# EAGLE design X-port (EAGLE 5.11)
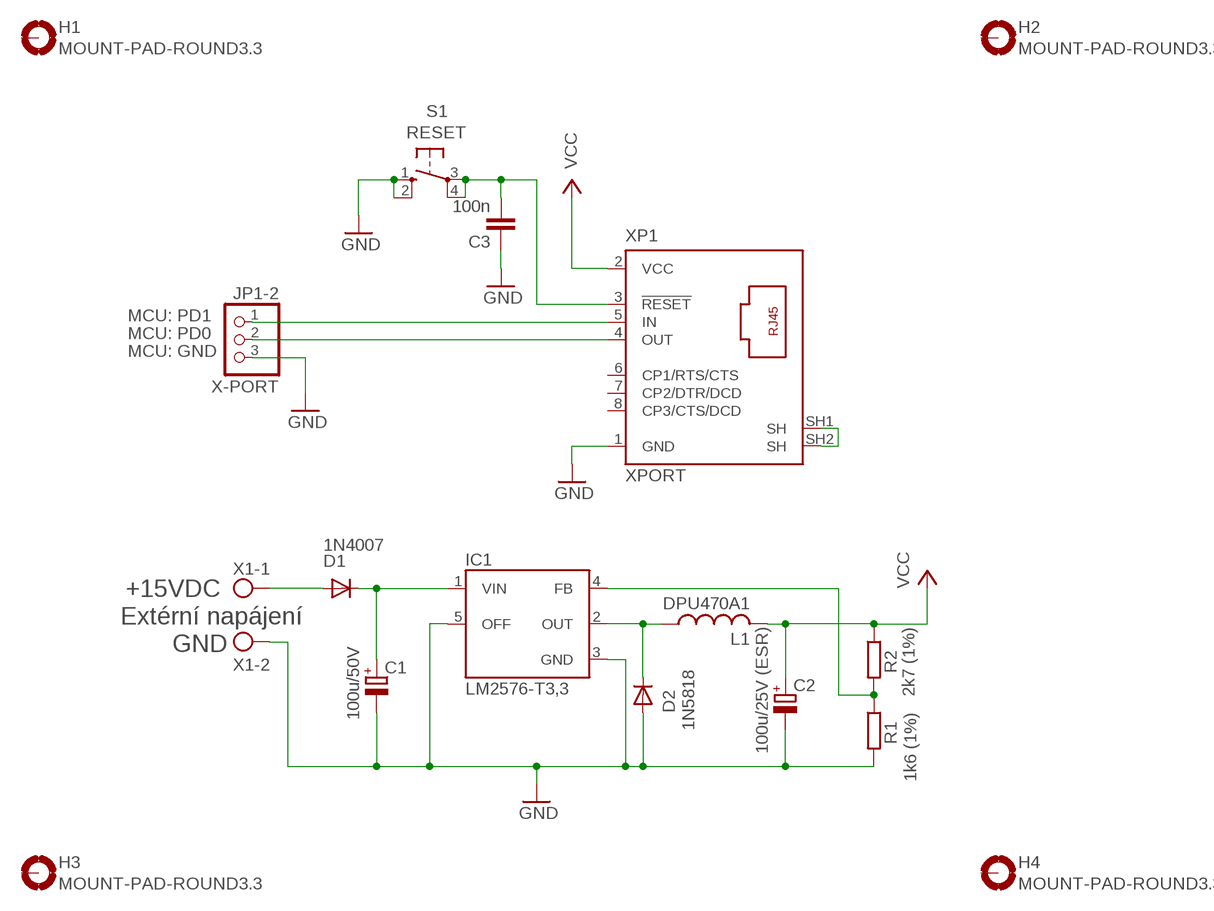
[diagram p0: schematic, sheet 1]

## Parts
C1  100u/50V  CPOL-EUE3.5-8  [E3,5-8]
C2  100u/25V (ESR)  CPOL-EUE3.5-8  [E3,5-8]
C3  100n  C-EU025-030X050  [C025-030X050]
D1  1N4007  1N4004  [DO41-10]
D2  1N5818  1N4004  [DO41-10]
H1  MOUNT-PAD-ROUND3.3  [3,3-PAD]
H2  MOUNT-PAD-ROUND3.3  [3,3-PAD]
H3  MOUNT-PAD-ROUND3.3  [3,3-PAD]
H4  MOUNT-PAD-ROUND3.3  [3,3-PAD]
IC1  LM2576-T3,3  LM2576T  [TO220-5]
JP1-2  X-PORT  PINHD-1X3  [1X03]
L1  DPU470A1  L-USIR-4  [IR-4]
R1  1k6 (1%)  R-EU_0207/7  [0207/7]
R2  2k7 (1%)  R-EU_0207/7  [0207/7]
S1  RESET  10-XX  [B3F-10XX]
X1  Extérní napájení  AK300/2  [AK300/2]
XP1  XPORT  [XPORT]

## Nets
GND: C1.- C2.- C3.1 D2.A IC1.3(GND) IC1.5(OFF) JP1-2.3 R1.2 S1.1(S) S1.2(S1) X1.2 XP1.1(GND)
N$2: JP1-2.1 XP1.5(IN)
N$4: C3.2 S1.3(P) S1.4(P1) XP1.3(!RESET)
N$17: JP1-2.2 XP1.4(OUT)
N$36: D1.A X1.1
N$37: C1.+ D1.C IC1.1(VIN)
N$41: IC1.4(FB) R1.1 R2.2
SHIELD: XP1.SH1(SH) XP1.SH2(SH)
VCC: C2.+ L1.2 R2.1 XP1.2(VCC)
VVV: D2.C IC1.2(OUT) L1.1
Unconnected: H1.B3,3(MOUNT) H2.B3,3(MOUNT) H3.B3,3(MOUNT) H4.B3,3(MOUNT) XP1.6(CP1/RTS/CTS) XP1.7(CP2/DTR/DCD) XP1.8(CP3/CTS/DCD)

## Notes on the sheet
- MCU: PD1
- MCU: PD0
- MCU: GND
- +15VDC
- GND

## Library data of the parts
C1 C2 = rcl:CPOL-EU: POLARIZED CAPACITOR, European symbol
C3 = rcl:C-EU: CAPACITOR, European symbol
D1 D2 = diode:1N4004: DIODE
H1-H4 = holes:MOUNT-PAD-ROUND: MOUNTING PAD, round
IC1 = v-reg-3:LM2576: National Semiconductor 3.0A "Simple Switcher"(c) 52kHz, Vout 1.23-37V (HV: 57V), Vin 40V (HV: 60V), 50µA standby current
JP1-2 = pinhead:PINHD-1X3: PIN HEADER
L1 = rcl:L-US: INDUCTOR, American symbol
R1 R2 = rcl:R-EU_: RESISTOR, European symbol
S1 = switch-omron:10-XX: OMRON SWITCH; MPN: B3F-1000; OC_FARNELL: 176432; OC_NEWARK: 36M3542
X1 = con-ptr500:AK300/2: CONNECTOR; OC_FARNELL: unknown; OC_NEWARK: unknown
XP1 = lantronix:XPORT: Serial to 10/100 Ethernet transceiver Source: http://www.lantronix.com/pdf/XPort_DS.pdf; OC_FARNELL: unknown; OC_NEWARK: unknown

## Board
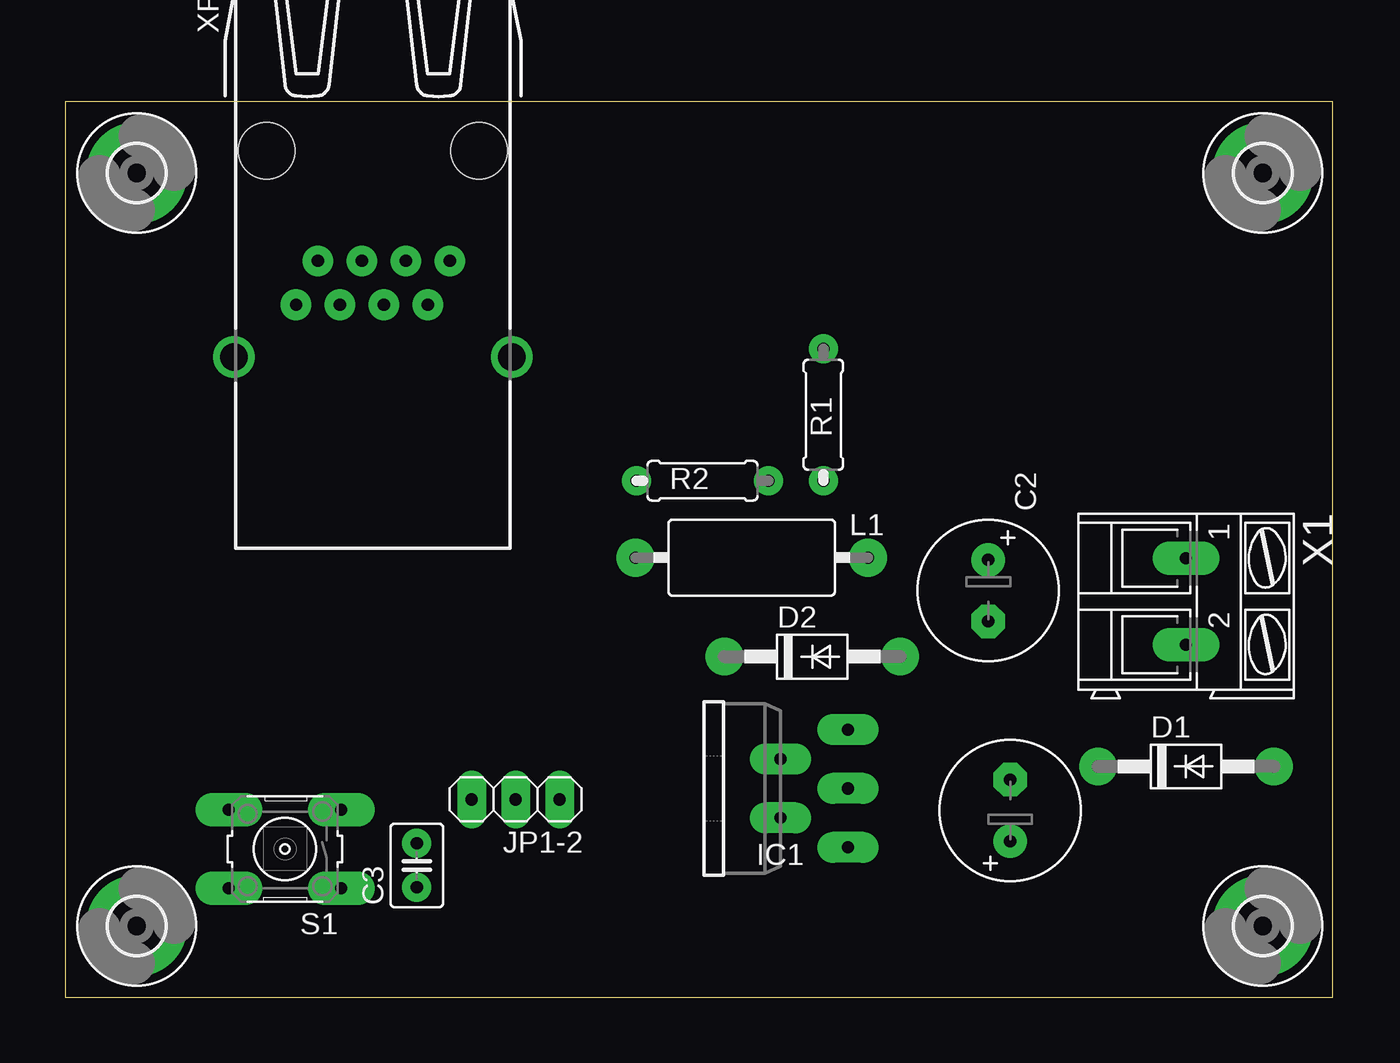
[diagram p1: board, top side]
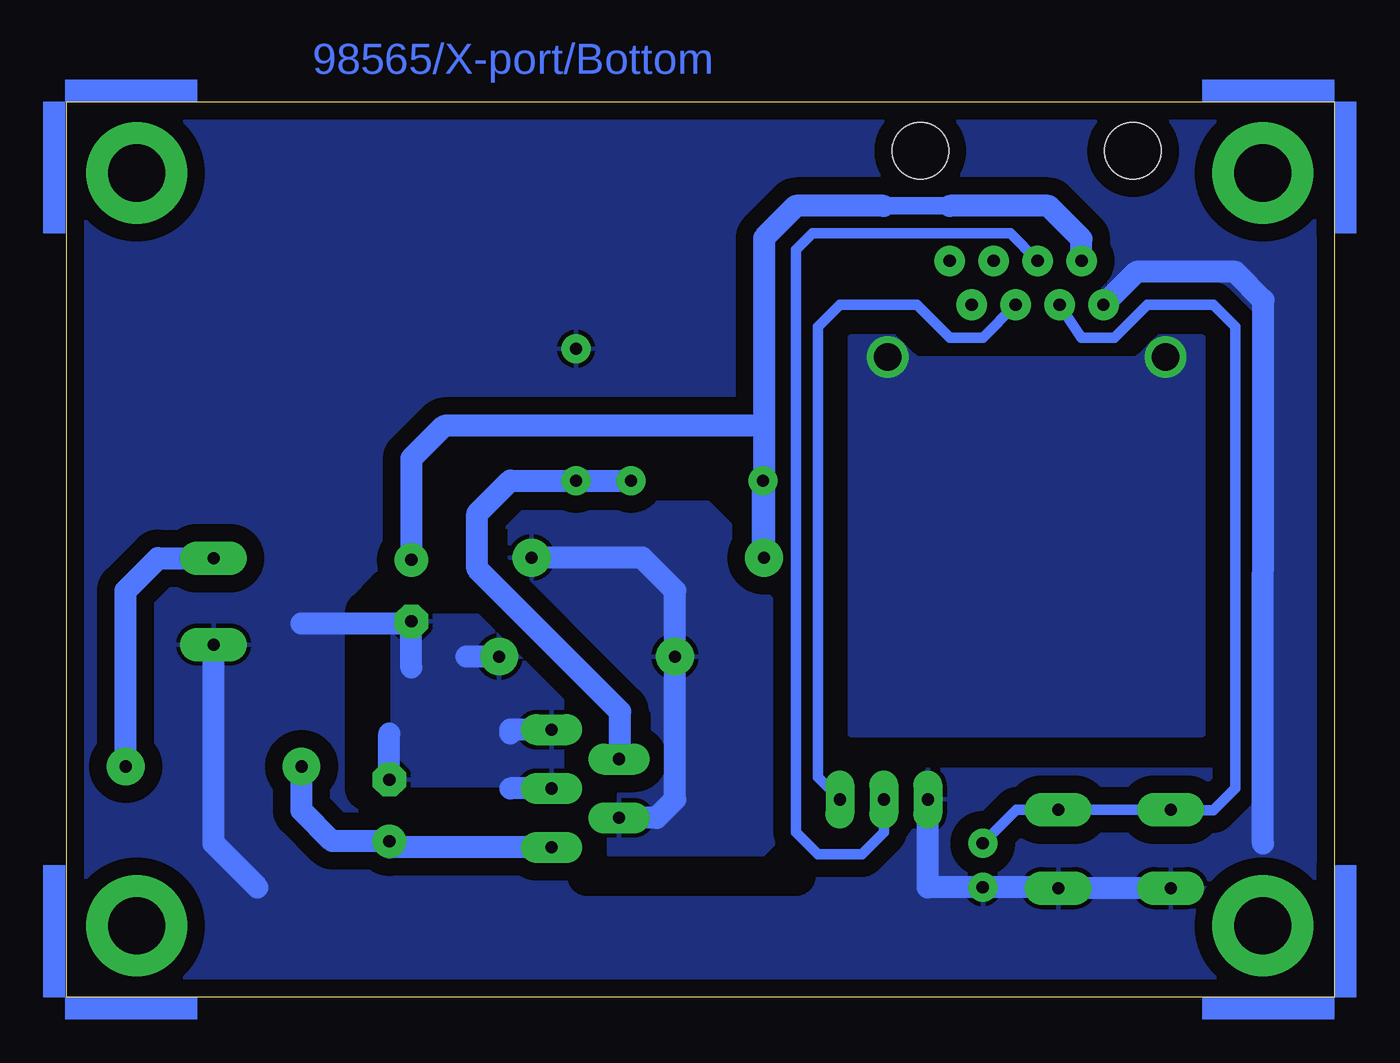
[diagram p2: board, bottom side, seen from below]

Size 73.27 x 51.73 mm. Coordinates in mm from the lower left corner, seen from the top.
Outline: 0,0 73.27,0 73.27,51.73 0,51.73 0,0
Copper layers (1*16): Top 0.035mm / dielectric 1.5mm / Bottom 0.035mm
Design rules "default *": minimum track width 10mil, minimum drill 24mil, track to track 12mil, track to pad 12mil, pad to pad 12mil, via to via 12mil, smd to smd 12mil, copper to edge 40mil, drill to drill 8mil, minimum pad ring 10mil, minimum via ring 8mil, stop-mask expansion 4mil, vias tented up to drill 0mil, thermal gap 10mil
bRestrict: 25 lines

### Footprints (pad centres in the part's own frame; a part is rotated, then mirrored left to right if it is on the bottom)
E3,5-8 = drill 0.7 pad 1.93 round: + -1.778,0 | drill 0.7 pad 1.93 octagon: - 1.778,0
C025-030X050 = drill 0.7 pad 1.676 round: 1 -1.27,0; 2 1.27,0
DO41-10 = drill 0.7 pad 2.184 round: A 5.08,0; C -5.08,0
3,3-PAD = drill 3.3 pad 5.842 round: B3,3 0,0
TO220-5 = drill 0.7 pad 1.778 long: 1 -3.4,-8.4; 2 -1.7,-4.5; 3 0,-8.4; 4 1.7,-4.5; 5 3.4,-8.4
1X03 = drill 0.7 pad 1.676 long: 1 -2.54,0; 2 0,0; 3 2.54,0
IR-4 = drill 0.7 pad 2.184 round: 1 -6.705,0; 2 6.73,0
0207/7 = drill 0.7 pad 1.676 round: 1 -3.81,0; 2 3.81,0
B3F-10XX = drill 0.7 pad 1.93 long: 1 -3.251,2.261; 2 3.251,2.261; 3 -3.251,-2.261; 4 3.251,-2.261
AK300/2 = drill 0.7 pad 1.93 long: 1 -2.515,0; 2 2.489,0
XPORT = drill 0.7 pad 1.778 round: 1 1.27,-4.445; 2 -1.27,-3.175; 3 1.27,-1.905; 4 -1.27,-0.635; 5 1.27,0.635; 6 -1.27,1.905; 7 1.27,3.175; 8 -1.27,4.445 | drill 1.6 pad 2.2 round: SH1 4.28,8.025; SH2 4.28,-8.025 | hole 3.25: -7.62,-6.15; -7.62,6.15

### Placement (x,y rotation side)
C1  54.61,10.79 90 top
C2  53.34,23.5 270 top
C3  20.32,7.62 90 top
D1  64.77,13.34 0 top
D2  43.18,19.68 0 top
H1  4.13,47.62 0 top
H2  69.22,47.62 0 top
H3  4.13,4.13 0 top
H4  69.22,4.13 0 top
IC1  36.83,12.06 90 top
JP1-2  26.04,11.43 180 top
L1  39.69,25.4 180 top
R1  43.81,33.66 90 top
R2  36.83,29.84 0 top
S1  12.7,8.57 180 top
U$5  [ANGLE-ARROW-NW1]  0,51.75 0 top
U$6  [ANGLE-ARROW-NW1]  73.34,51.75 270 top
U$7  [ANGLE-ARROW-NW1]  0,0 90 top
U$8  [ANGLE-ARROW-NW1]  73.34,0 180 top
X1  64.77,22.86 270 top
XP1  17.78,41.27 270 top

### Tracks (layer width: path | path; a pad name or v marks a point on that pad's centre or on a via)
GND
  Bottom 1.27: XP1.1 11.43,41.91 5.71,41.91 4.09,40.28 4.13,8.89 | JP1-2.3 23.5,6.35 C3.1 15.99,6.35 S1.1 S1.2 | 62.23,6.35 64.77,8.89 X1.2 | IC1.3 47.62,12.06 | IC1.5 47.62,15.46 47.62,15.24 | D2.A 50.16,19.68 | 53.34,19.05 53.34,21.59 | 53.34,21.59 C2.- | C1.- 54.61,15.24 | 53.34,21.59 59.69,21.59
  pour Bottom (isolate 1.016): 0,51.44 73.03,51.44 73.03,0 0,0 0,0.64
N$1
  pour Bottom (isolate 1.016): 38.73,14.61 48.26,24.13 48.26,27.94 47.62,28.57 38.1,28.57 32.38,22.86 32.38,9.53 33.02,8.89 41.91,8.89 42.55,9.53 42.55,11.43 41.91,12.06 39.37,12.06 38.73,12.7
N$2
  Bottom 0.61: JP1-2.1 29.84,12.7 29.84,38.73 28.57,40.01 24.13,40.01 22.23,38.1 20.32,38.1 XP1.5
N$3
  pour Bottom (isolate 1.016): 39.37,16.51 48.26,25.4 48.26,27.94 47.62,28.57 36.2,28.57 34.92,27.3 34.92,24.77 32.38,22.23 32.38,8.89 33.66,7.62 41.27,7.62 42.55,8.89 42.55,11.43 41.91,12.06 40.01,12.06 39.37,12.7
N$4
  Bottom 0.61: XP1.3 14.61,38.1 12.7,38.1 10.79,40.01 6.99,40.01 5.71,38.73 5.71,12.06 6.99,10.79 7.51,10.79 | 7.51,10.79 7.62,10.79 | 7.51,10.79 S1.4 S1.3 18.38,10.83 C3.2
N$17
  Bottom 0.61: XP1.4 18.73,44.13 30.16,44.13 31.11,43.18 31.11,9.53 29.84,8.26 27.3,8.26 26.04,9.53 JP1-2.2
N$36
  Bottom 1.27: X1.1 67.97,25.38 69.85,23.5 D1.A
N$37
  Bottom 1.27: IC1.1 54.61,8.66 C1.+ 57.91,9.02 59.69,10.79 D1.C
N$41
  Bottom 1.27: IC1.4 41.27,13.77 41.27,16.51 49.53,24.77 49.53,27.94 47.62,29.84 R1.1 R2.2
SHIELD
  pour Bottom (no thermals): 7.62,38.1 10.16,38.1 11.43,36.83 24.13,36.83 25.4,38.1 27.94,38.1 27.94,15.24 7.62,15.24
VCC
  Bottom 1.016: 22.23,45.72 26.04,45.72
  Bottom 1.27: R2.1 33.02,25.4 L1.2 32.96,26.1 | 26.04,45.72 31.11,45.72 32.96,43.88 32.96,33.02 | 22.23,45.72 16.51,45.72 14.61,43.81 XP1.2 | 32.96,33.02 32.96,26.1 | 32.96,26.1 33.02,26.04 | C2.+ 53.34,31.11 51.44,33.02 32.96,33.02
VVV
  Bottom 1.27: L1.1 40.01,25.4 38.1,23.5 D2.C 38.1,11.43 39.16,10.37 IC1.2
  pour Bottom (isolate 1.016): 42.55,10.79 42.55,11.43 41.91,12.06 40.01,12.06 39.37,12.7 39.37,16.51 47.62,24.77 47.62,27.3 46.35,28.57 36.2,28.57 34.92,27.3 34.92,24.77 32.38,22.23 32.38,9.53 34.29,7.62 41.27,7.62 42.55,8.89

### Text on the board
Bottom: 98565/X-port/Bottom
